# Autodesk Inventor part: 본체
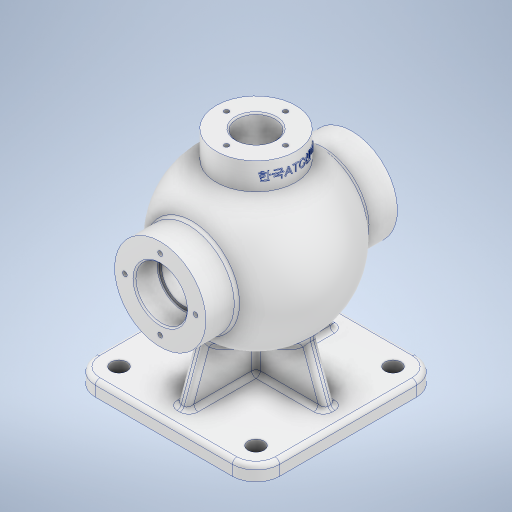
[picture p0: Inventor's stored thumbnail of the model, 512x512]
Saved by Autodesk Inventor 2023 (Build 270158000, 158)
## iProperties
Created: 2023-07
Part Number: 본체
Material: 알루미늄 6061
Document SubType Name: Modeling
Designer: Owner
Density: 2.7 g/cm^3
Appearance: 알루미늄 - 평지
Mass: 1526.51 g
Surface Area: 1174.33 cm^2
Volume: 565.376 cm^3
Author: Owner
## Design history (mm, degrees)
sketch "스케치1"
  geometry: L1 (62.5, 62.5)-(-62.5, 62.5); L2 (-62.5, 62.5)-(-62.5, -62.5); L3 (-62.5, -62.5)-(62.5, -62.5); L4 (62.5, -62.5)-(62.5, 62.5); L5 (62.5, 62.5)-(-62.5, -62.5); L6 (-62.5, 62.5)-(62.5, -62.5); 1 further point
  constraints: 12 end point, 2 midpoint, 2 parallel, 1 horizontal, 1 perpendicular
  dimensions: "d0" = 125 distance of L2.end L3.end; "d1" = 125 distance of L1.end L2.end
extrude "돌출1" new body sketch "스케치1" distance "d2" = 10; taper "d3" = 0 deg
sketch "스케치2"
  geometry: L1 (85, 65)-(85, -65); L2 (85, 65)-(116, 65); L3 (116, 65)-(116, 44.215); L4 (85, -65)-(116, -65); L5 (116, -65)-(116, -44.215); A1 r 54 centre (85, 0) between (116, -44.215) and (116, 44.215); 2 further points
  constraints: 10 end point, 2 horizontal, 2 perpendicular, 2 point on circle, 1 centre point, 1 coincident, 1 horizontal alignment, 1 midpoint, 1 parallel, 1 vertical
  dimensions: "d12" = 130 distance of L1.start L1.end; "d13" = 85 distance of point (0, 0) point (85, 0); "d14" = 108 diameter of A1; "d16" = 62 diameter of L5 L1
revolve "회전1" sketch "스케치2" stored, may be unused: angle "d17" = 90 deg
sketch "스케치3"
  geometry: C1 r 31 at (0, 0) reference; 2 further points
  constraints: 1 coincident
hole "구멍1" sketch "스케치3" at (0, 0) diameter "d18" = 35; stored, may be unused: countersink angle "d22" = 90 deg, drill point angle "d24" = 0 deg; dims "d19" = 6, "d20" = 4, "d21" = 2, "d23" = 16
sketch "스케치4"
  geometry: L1 (58.87, 32.713)-(10, 50.5); L2 (58.87, -32.713)-(10, -50.5); L3 (0, -62.5)-(10, -62.5) reference; L4 (67.5, 65)-(67.5, 49) reference; L5 (67.5, 49)-(102.5, 49) reference; L6 (102.5, 49)-(102.5, 65) reference; L7 (102.5, 65)-(116, 65) reference; L8 (116, 65)-(116, 44.215) reference; L9 (116, -44.215)-(116, -65) reference; L10 (116, -65)-(54, -65) reference; L11 (54, -65)-(54, -44.215) reference; L12 (54, 44.215)-(54, 65) reference; L13 (54, 65)-(67.5, 65) reference; L14 (10, -62.5)-(0, -62.5) reference; L15 (0, -62.5)-(0, 62.5) reference; L16 (0, 62.5)-(10, 62.5) reference; L17 (10, 62.5)-(10, -62.5) reference; L18 (58.87, 32.713)-(58.87, -32.713); A1 r 54 centre (85, 0) between (116, -44.215) and (116, 44.215) reference; A2 r 54 centre (85, 0) between (54, 44.215) and (54, -44.215) reference; 1 further point
  constraints: 6 end point, 2 point on line, 1 equal length
  dimensions: "d25" = 20 deg angle of L3 L2; "d26" = 20 deg angle of L1 L16; "d27" = 12 vertical distance of L15.end L1.end; "d29" = 12 distance from line of L14 L2.end; "d30" = 48.87013 horizontal distance of L1.start L1.end
  node "절단 모서리 투영1"
fillet "모깎기1" dims "d28" = 16
feature "리브1" dims "d31" = 1, "d32" = 8, "d33" = 0, "d34" = 0, "d35" = 1, "d36" = 1
sketch "스케치5"
  geometry: L1 (32.433, 59.64)-(50.5, 10); L2 (-32.433, 59.64)-(-50.5, 10); L3 (62.5, 0)-(-62.5, 0) reference; L4 (-62.5, 0)-(-62.5, 10) reference; L5 (-62.5, 10)-(-4, 10) reference; L6 (-4, 10)-(-4, 31.148) reference; L7 (4, 31.148)-(4, 10) reference; L8 (4, 10)-(62.5, 10) reference; L9 (62.5, 10)-(62.5, 0) reference; L10 (-32.433, 59.64)-(32.433, 59.64); A1 r 54 centre (0, 85) between (4, 31.148) and (-4, 31.148) reference; 1 further point
  constraints: 6 end point, 2 point on line, 1 horizontal
  dimensions: "d37" = 20 deg angle of L1 L9; "d38" = 20 deg angle of L2 L4; "d39" = 12 horizontal distance of L2.end L3.end; "d40" = 12 horizontal distance of L3.start L1.end; "d41" = 59.63953 distance between parallel lines of L3 L10
feature "리브2" sketch "스케치5" dims "d42" = 1, "d43" = 8, "d44" = 0, "d45" = 0, "d46" = 1, "d47" = 1
fillet "모깎기2" dims "d48" = 3
fillet "모깎기3" dims "d49" = 3
fillet "모깎기4" dims "d50" = 3
sketch "스케치6"
  geometry: C1 r 5.5 at (46.5, -46.5); C2 r 5.5 at (46.5, 46.5); C3 r 5.5 at (-46.5, -46.5); C4 r 5.5 at (-46.5, 46.5); A1 r 13 centre (46.5, -46.5) between (46.5, -59.5) and (59.5, -46.5) reference; A2 r 13 centre (46.5, 46.5) between (59.5, 46.5) and (46.5, 59.5) reference; A3 r 13 centre (-46.5, 46.5) between (-46.5, 59.5) and (-59.5, 46.5) reference; A4 r 13 centre (-46.5, -46.5) between (-59.5, -46.5) and (-46.5, -59.5) reference; 1 further point
  constraints: 4 centre point, 4 coincident
  dimensions: "d51" = 11 diameter of C1; "d52" = 11 diameter of C4; "d53" = 11 diameter of C2; "d54" = 11 diameter of C3
extrude "돌출2" cut sketch "스케치6" stored distance "d55" = 10; taper "d56" = 0 deg
sketch "스케치7"
  geometry: L1 (67.5, 65)-(67.5, 49) reference; L2 (67.5, 49)-(102.5, 49) reference; L3 (102.5, 49)-(102.5, 65) reference; L4 (102.5, 65)-(116, 65) reference; L5 (116, 65)-(116, 44.215) reference; L6 (116, -44.215)-(116, -65) reference; L7 (116, -65)-(54, -65) reference; L8 (54, -65)-(54, -44.215) reference; L9 (44.231, -38.041)-(11.974, -49.782) reference; L10 (10, -52.601)-(10, -59.5) reference; L11 (7, -62.5)-(0, -62.5) reference; L12 (0, -62.5)-(0, 62.5) reference; L13 (0, 62.5)-(7, 62.5) reference; L14 (10, 59.5)-(10, 52.601) reference; L15 (11.974, 49.782)-(44.231, 38.041) reference; L16 (54, 44.215)-(54, 65) reference; L17 (54, 65)-(67.5, 65) reference; L18 (54, -65)-(116, -65) reference; L19 (85, -65)-(85, 65); L20 (100, 49)-(100, 41.364); L21 (102.5, -65)-(102.5, -49); L22 (102.5, -49)-(100, -49); L23 (100, -49)-(100, -41.364); A1 r 54 centre (85, 0) between (116, -44.215) and (116, 44.215) reference; A2 r 54 centre (85, 0) between (47.349, -38.709) and (54, -44.215) reference; A3 r 3 centre (45.257, -40.86) between (47.349, -38.709) and (44.231, -38.041) reference; A4 r 3 centre (13, -52.601) between (11.974, -49.782) and (10, -52.601) reference; A5 r 3 centre (7, -59.5) between (7, -62.5) and (10, -59.5) reference; A6 r 3 centre (7, 59.5) between (10, 59.5) and (7, 62.5) reference; A7 r 3 centre (13, 52.601) between (10, 52.601) and (11.974, 49.782) reference; A8 r 3 centre (45.257, 40.86) between (44.231, 38.041) and (47.349, 38.709) reference; A9 r 54 centre (85, 0) between (54, 44.215) and (47.349, 38.709) reference; A10 r 44 centre (85, 0) between (100, -41.364) and (100, 41.364); 4 further points
  constraints: 10 end point, 3 perpendicular, 2 point on circle, 2 point on line, 2 vertical, 1 centre point, 1 coincident, 1 midpoint
  dimensions: "d57" = 88 diameter of A10; "d59" = 15 distance between parallel lines of L19 L20; "d60" = 15 distance between parallel lines of L19 L23; "d61" = 17.5 distance between parallel lines of L19 L21; "d62" = 16 distance between parallel lines of L7 L22
revolve "회전2" sketch "스케치7" stored, may be unused: angle "d63" = 90 deg
node "작업 평면1"
sketch "스케치8"
  geometry: C1 r 27 at (0, 0); 1 further point
  constraints: 1 centre point, 1 coincident
  dimensions: "d65" = 54 diameter of C1
extrude "돌출3" join sketch "스케치8" stored distance "d66" = 10; taper "d67" = 0 deg
sketch "스케치9"
  geometry: C1 r 27 at (0, 0) reference; 2 further points
  constraints: 1 coincident
hole "구멍2" sketch "스케치9" at (0, 0) diameter "d68" = 26; stored, may be unused: countersink angle "d72" = 90 deg, drill point angle "d74" = 0 deg; dims "d69" = 6, "d70" = 4, "d71" = 2, "d73" = 40
sketch "스케치10"
  geometry: C1 r 17.5 at (0, 0) reference; 2 further points
  constraints: 1 vertical alignment
  dimensions: "d75" = 24 distance of C1.centre point (0, 24)
hole "구멍3" sketch "스케치10" at (0, 24) diameter "d76" = 3.242; stored, may be unused: countersink angle "d80" = 90 deg, drill point angle "d82" = 118 deg; dims "d77" = 12, "d78" = 4, "d79" = 2, "d81" = 15
sketch "스케치11"
  geometry: C1 r 13 at (0, 0) reference; 1 further point
  constraints: 1 horizontal alignment
  dimensions: "d86" = 20 distance of C1.centre point (-20, 0)
hole "구멍4" sketch "스케치11" at (-20, 0) diameter "d87" = 3.242; stored, may be unused: countersink angle "d91" = 90 deg, drill point angle "d93" = 118 deg; dims "d88" = 9, "d89" = 4, "d90" = 2, "d92" = 11
fillet "모깎기5" dims "d97" = 3
chamfer "모따기1" distance "d98" = 1; stored, may be unused: second distance "d99" = 2, angle "d100" = 45 deg
chamfer "모따기2" distance "d101" = 1; stored, may be unused: second distance "d102" = 2, angle "d103" = 45 deg
fillet "모깎기6" dims "d104" = 0.6
fillet "모깎기7" dims "d105" = 0.6
node "작업 평면2"
sketch "스케치12"
  geometry: 1 further point
sketch "스케치13"
  geometry: L1 (150, -27)-(150, 27) reference; 2 further points
  constraints: 1 horizontal alignment, 1 other
  dimensions: "d107" = 9 distance from line of point (141, 0) L1
feature "엠보싱1" sketch "스케치13" dims "d0" = 125, "d1" = 125, "d33" = 0, "d108" = 0.5, "d109" = 0
feature "ư耀Ʋ耀ƴ耀ƶ耀Ƹ耀ƺ耀Ƽ耀ƾ耀" dims "d0" = 125, "d1" = 125, "d2" = 10, "d3" = 0, "d12" = 130, "d13" = 85, "d14" = 108, "d16" = 62, "d17" = 90 deg, "d18" = 35, "d19" = 6, "d20" = 4, "d21" = 2, "d22" = 90 deg, "d23" = 16, "d24" = 0, "d25" = 20 deg, "d26" = 20 deg, "d27" = 12, "d28" = 16, "d29" = 12, "d30" = 48.87013, "d31" = 1, "d32" = 8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
node "솔리드1"
pattern_circular "원형 패턴1" dims angle "d84" = 360 deg
mirror "미러1"
pattern_circular "원형 패턴2" dims angle "d95" = 360 deg
node "절단 모서리 투영2"
node "절단 모서리 투영3"
feature "A9D066F2-1C7D-4E18-AEED-F7BC21143FA4" dims "d18" = 35, "d19" = 6, "d20" = 4, "d21" = 2, "d22" = 90 deg, "d23" = 16, "d24" = 0
